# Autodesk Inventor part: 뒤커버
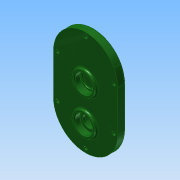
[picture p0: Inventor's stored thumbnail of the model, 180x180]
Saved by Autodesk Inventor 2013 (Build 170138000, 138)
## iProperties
Created: 2016-12
Part Number: 뒤커버
Material: 알루미늄 6061
Document SubType Name: Modeling
Designer: mduedu
Density: 2.71 g/cm^3
Mass: 236.427 g
Surface Area: 240.702 cm^2
Volume: 87.2423 cm^3
Author: mduedu
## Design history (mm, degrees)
sketch "스케치1"
  geometry: L1 (40, -25)-(40, 25); L2 (-40, 25)-(-40, -25); L3 (-40, -25)-(40, 25); L4 (40, -25)-(-40, 25); A1 r 40 centre (0, 25) between (40, 25) and (-40, 25); A2 r 40 centre (0, -25) between (-40, -25) and (40, -25); 1 further point
  constraints: 8 end point, 4 point on circle, 4 tangent, 2 centre point, 2 midpoint, 1 parallel, 1 vertical
  dimensions: "d0" = 130 dimension on A2 A1; "d2" = 80 distance between parallel lines of L1 L2
extrude "돌출1" new body sketch "스케치1" distance "d3" = 10; taper "d4" = 0 deg
sketch "스케치2"
  geometry: C1 r 14 at (0, 11); 1 further point
  constraints: 1 centre point, 1 vertical alignment
  dimensions: "d5" = 28 diameter of C1; "d6" = 11 distance of C1.centre point (0, 0)
extrude "돌출2" join sketch "스케치2" distance "d7" = 3; taper "d8" = 0 deg
sketch "스케치3"
  geometry: C1 r 14 at (0, -33.1); C2 r 14 at (0, 11) reference; 1 further point
  constraints: 1 centre point, 1 vertical alignment
  dimensions: "d9" = 28 diameter of C1; "d69" = 44.1 distance of C1.centre C2.centre
extrude "돌출3" join sketch "스케치3" distance "d11" = 3; taper "d12" = 0 deg
hole "구멍1" diameter "d15" = 22; stored, may be unused: countersink angle "d19" = 90 deg, drill point angle "d21" = 0 deg; dims "d13" = 10, "d14" = 10, "d16" = 6, "d17" = 4, "d18" = 2, "d20" = 7
hole "구멍2" diameter "d24" = 18; stored, may be unused: countersink angle "d28" = 90 deg, drill point angle "d30" = 0 deg; dims "d22" = 10, "d23" = 10, "d25" = 6, "d26" = 4, "d27" = 2, "d29" = 1
hole "구멍3" diameter "d33" = 22; stored, may be unused: countersink angle "d37" = 90 deg, drill point angle "d39" = 0 deg; dims "d31" = 10, "d32" = 10, "d34" = 6, "d35" = 4, "d36" = 2, "d38" = 7
sketch "스케치4"
  geometry: C1 r 14 at (0, -33.1) reference; C2 r 18 at (0, -33.1); 1 further point
  constraints: 1 centre point, 1 coincident
  dimensions: "d40" = 36 diameter of C2
extrude "돌출4" join sketch "스케치4" distance "d41" = 4; taper "d42" = 0 deg
hole "구멍4" diameter "d45" = 22; stored, may be unused: countersink angle "d49" = 90 deg, drill point angle "d51" = 0 deg; dims "d43" = 10, "d44" = 10, "d46" = 6, "d47" = 4, "d48" = 2, "d50" = 7
hole "구멍5" diameter "d54" = 15; stored, may be unused: countersink angle "d58" = 90 deg, drill point angle "d60" = 0 deg; dims "d52" = 10, "d53" = 10, "d55" = 6, "d56" = 4, "d57" = 2, "d59" = 7
fillet "모깎기1" dims "d61" = 0.3
fillet "모깎기2" dims "d62" = 2
chamfer "모따기1" distance "d63" = 1; stored, may be unused: second distance "d64" = 2, angle "d65" = 45 deg
fillet "모깎기3" dims "d66" = 2
fillet "모깎기4" dims "d67" = 2
fillet "모깎기5" dims "d68" = 2
sketch "스케치5"
  geometry: L1 (-40, 25)-(-40, -25) reference; L2 (40, -25)-(40, 25) reference; L3 (35, 25)-(35, -25); L4 (-35, -25)-(-35, 25); A1 r 40 centre (0, 25) between (40, 25) and (-40, 25) reference; A2 r 40 centre (0, -25) between (-40, -25) and (40, -25) reference; A3 r 35 centre (0, 25) between (35, 25) and (-35, 25); A4 r 35 centre (0, -25) between (-35, -25) and (35, -25); 2 further points
  constraints: 5 point on circle, 4 end point, 2 centre point, 1 vertical alignment, 3 other
  dimensions: "d70" = 5 distance between parallel lines of L2 L3
sketch "스케치6"
  geometry: 1 further point
hole "구멍6" sketch "스케치6" at (0, 60) diameter "d71" = 4.5; stored, may be unused: countersink angle "d75" = 90 deg, drill point angle "d77" = 0 deg; dims "d72" = 6, "d73" = 8, "d74" = 4.6, "d76" = 8
node "솔리드1"
pattern_linear "직사각형 패턴1"
